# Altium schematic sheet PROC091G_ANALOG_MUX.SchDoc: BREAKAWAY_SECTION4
size 431 x 279 mm; Date: Not shown in title block; ApprovedBy: Not shown in title block; CheckedBy: Not shown in title block; Author: Not shown in title block; CompanyName: Not shown in title block; DrawnBy: Antony/Bala; Engineer: Not shown in title block; Organization: Not shown in title block; Address1: Not shown in title block; Address2: Not shown in title block; Address3: Not shown in title block; Address4: Not shown in title block; DocumentNumber: 10; Revision: Use project parameter SCH_Rev; SheetNumber: 10; SheetTotal: 12; PageSetup: Record=PageOptions¦CenterHorizontal=True¦CenterVertical=True¦PrintScale=1.00¦XCorrection=1.00¦YCorrection=1.00¦PrintKind=0¦BorderSize=5000000¦LeftOffset=0¦BottomOffset=0¦Orientation=2¦PaperLength=1000¦PaperWidth=1000¦Scale=100¦PaperSource=15¦PrintQuality=600¦MediaType=1¦DitherType=10¦PaperKind=Letter¦PrintScaleMode=1
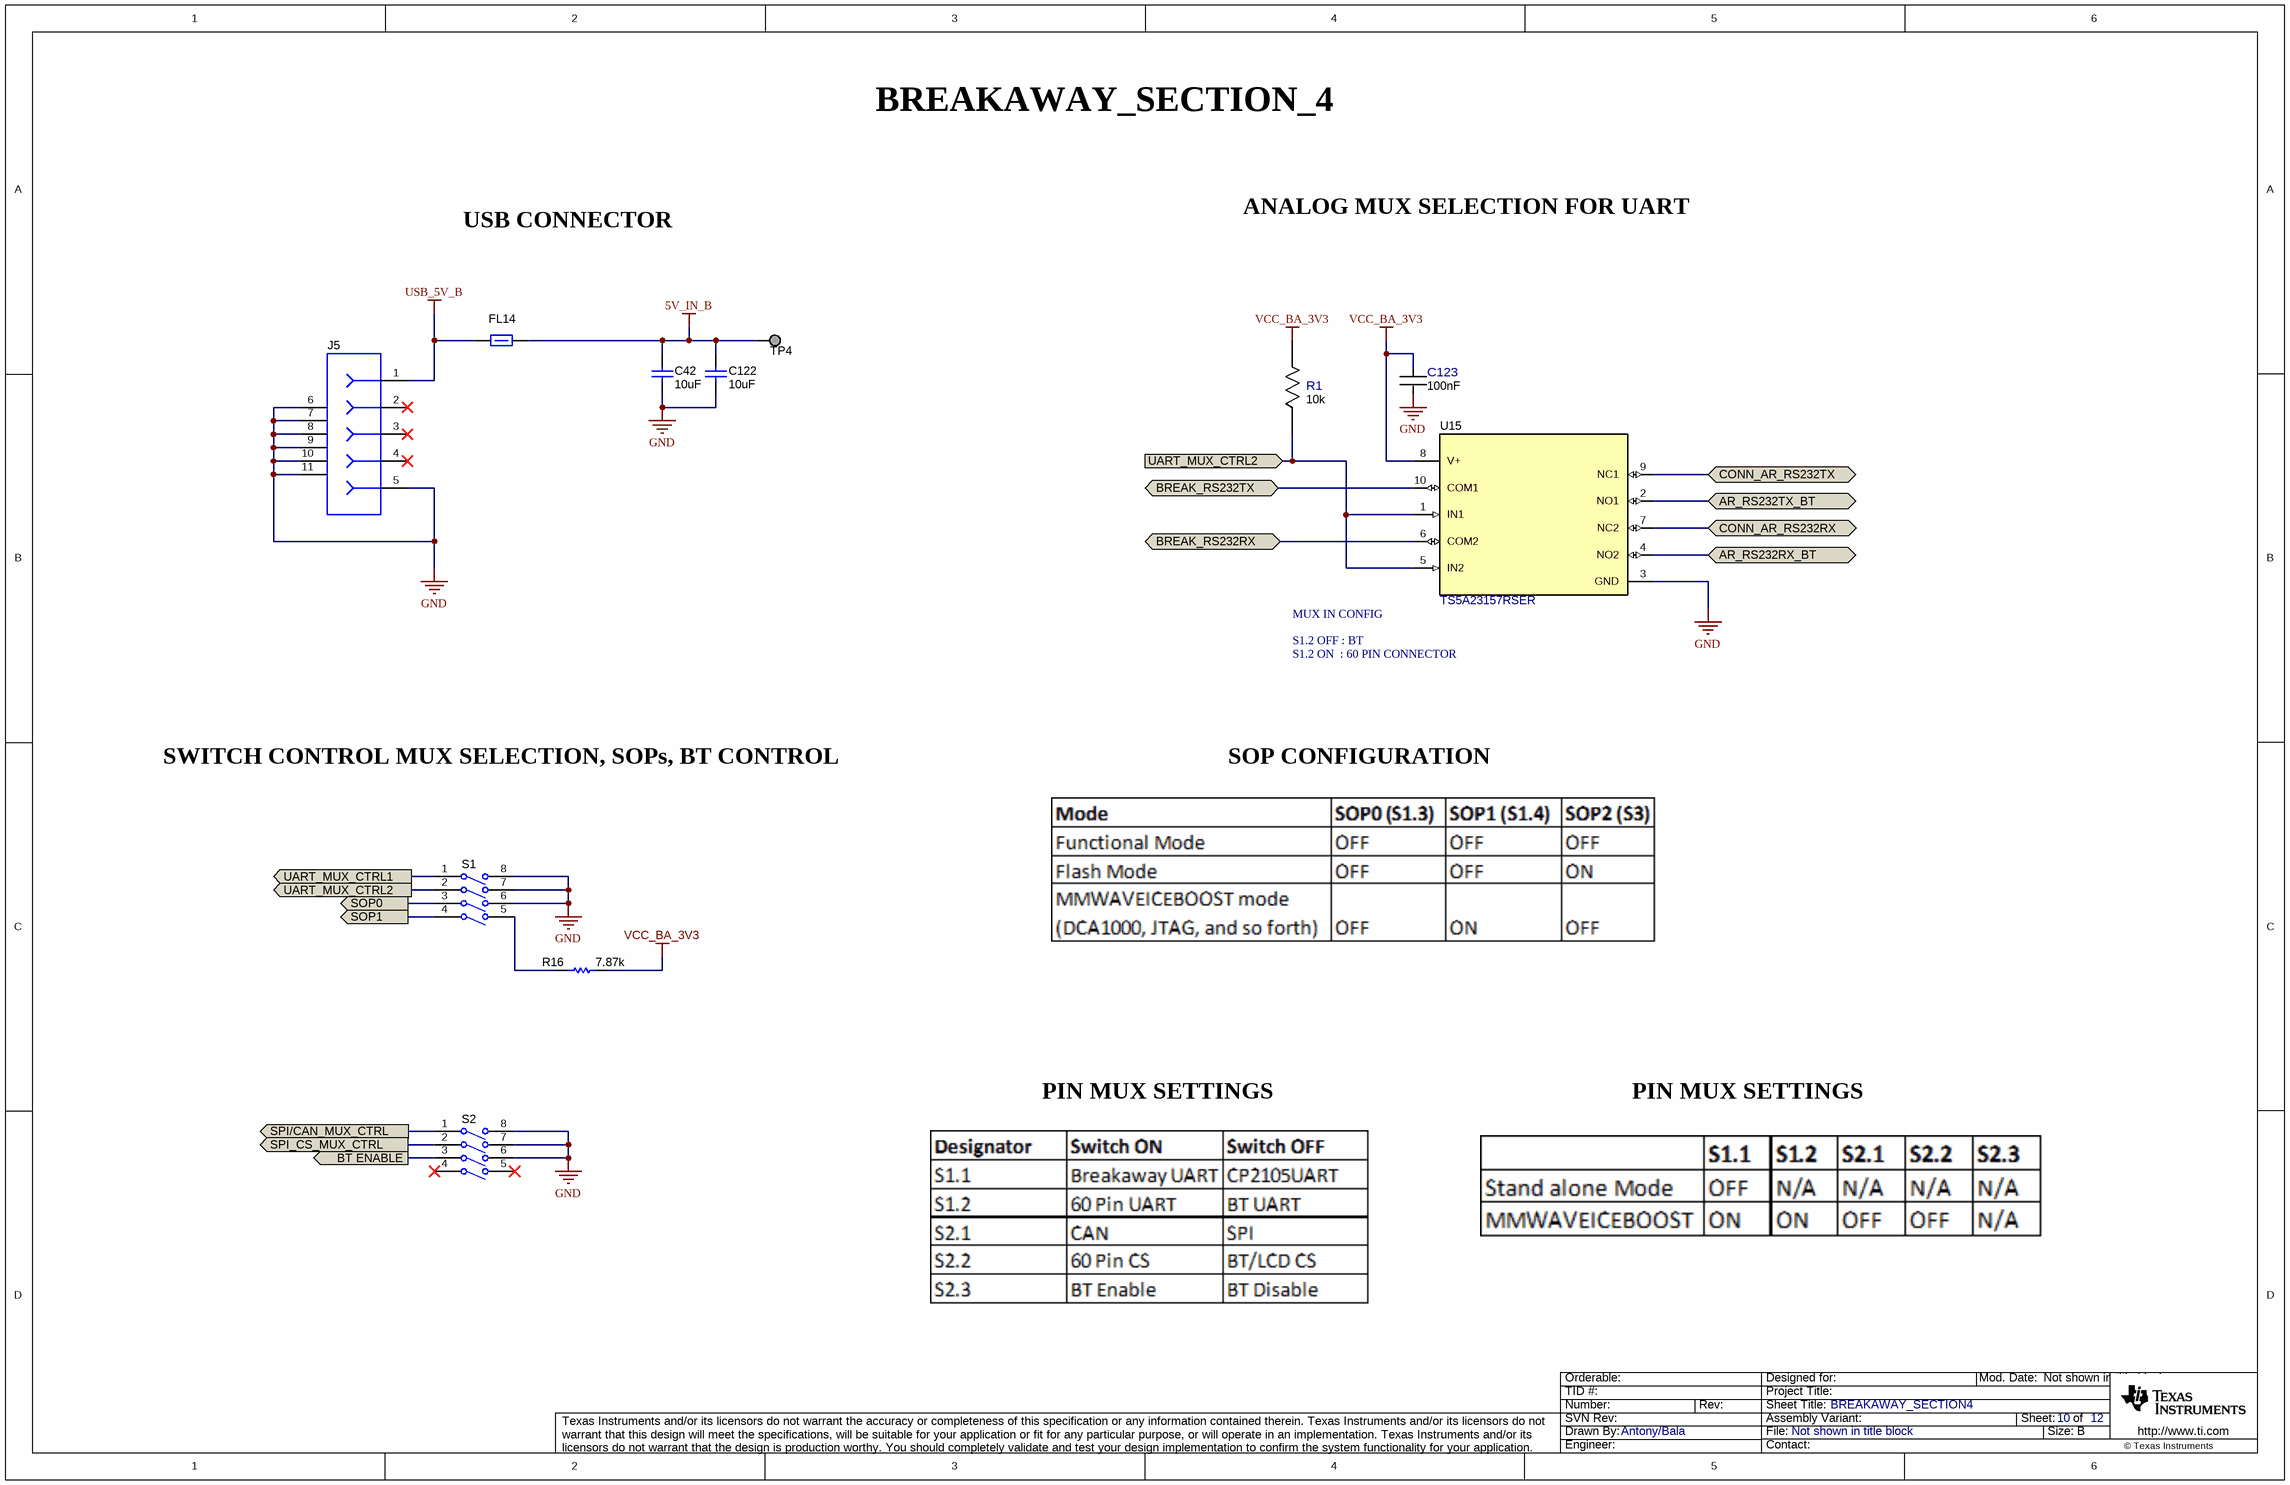
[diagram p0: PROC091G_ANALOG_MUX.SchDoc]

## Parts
C42  value 10uF  [0402_070]  (hidden comment: CL05A106MP5NUNC)
C122  value 10uF  [0402_070]  (hidden comment: CL05A106MP5NUNC)
C123  Cap_F: 100nF  [FP-GRM033R6YA104KE14D_0201 (0603 Metric)-IPC_C]  (hidden comment: GRM033R6YA104KE14D)
FL14  BLM15PD300SZ1D  [0402L]  (value not drawn)
J5  105017-0001  [CONN_105017-0001]  (value not drawn)
R1  Res_ohm: 10k  [FP-RR0306P-103-D_0201-IPC_C]  (hidden comment: RR0306P-103-D)
R16  value 7.87k  [0201L]  (hidden comment: RC0201FR-077K87L)
S1  218-4LPST  [SW_218-4LPST]  (value not drawn)
S2  218-4LPST  [SW_218-4LPST]  (value not drawn)
TP4  TESTPOINT  [TP_25MIL-SMT]  (value not drawn)  (no BOM)
U15  TS5A23157RSER  [RSE0010A]

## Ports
AR_RS232RX_BT (bidir), AR_RS232TX_BT (bidir), BREAK_RS232RX (bidir), BREAK_RS232TX (bidir), BT ENABLE (out), CONN_AR_RS232RX (bidir), CONN_AR_RS232TX (bidir), SOP0 (out), SOP1 (out), SPI/CAN_MUX_CTRL (out), SPI_CS_MUX_CTRL (out), UART_MUX_CTRL1 (out), UART_MUX_CTRL2 (in), UART_MUX_CTRL2 (out)

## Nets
5V_IN_B: C42.2 C122.1 FL14.2 TP4.1
GND: C42.1 C122.2 C123.2 J5.5 J5.6 J5.7 J5.8 J5.9 J5.10 J5.11 S1.6(B3) S1.7(B2) S1.8(B1) S2.6(B3) S2.7(B2) S2.8(B1) U15.3(GND)
USB_5V_B: FL14.1 J5.1
VCC_BA_3V3: C123.1 R1.2 R16.1 U15.8(V+)
AR_RS232RX_BT: U15.4(NO2) ; port AR_RS232RX_BT
AR_RS232TX_BT: U15.2(NO1) ; port AR_RS232TX_BT
BREAK_RS232RX: U15.6(COM2) ; port BREAK_RS232RX
BREAK_RS232TX: U15.10(COM1) ; port BREAK_RS232TX
BT ENABLE: S2.3(A3) ; port BT ENABLE
CONN_AR_RS232RX: U15.7(NC2) ; port CONN_AR_RS232RX
CONN_AR_RS232TX: U15.9(NC1) ; port CONN_AR_RS232TX
SOP0: S1.3(A3) ; port SOP0
SOP1: S1.4(A4) ; port SOP1
SPI/CAN_MUX_CTRL: S2.1(A1) ; port SPI/CAN_MUX_CTRL
SPI_CS_MUX_CTRL: S2.2(A2) ; port SPI_CS_MUX_CTRL
UART_MUX_CTRL1: S1.1(A1) ; port UART_MUX_CTRL1
UART_MUX_CTRL2: R1.1 S1.2(A2) U15.1(IN1) U15.5(IN2) ; port UART_MUX_CTRL2
NetR16_2: R16.2 S1.5(B4)

Not connected (* = marked no-connect by the designer): J5 2* 3* 4*; S2 4(A4)* 5(B4)*

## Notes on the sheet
- BREAKAWAY_SECTION_4
- USB CONNECTOR
- ANALOG MUX SELECTION FOR UART
- MUX IN CONFIG
- S1.2 ON  : 60 PIN CONNECTOR
- S1.2 OFF : BT
- SWITCH CONTROL MUX SELECTION, SOPs, BT CONTROL
- SOP CONFIGURATION
- PIN MUX SETTINGS

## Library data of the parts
C42 C122 = CMP-0006339-4: CAP, CERM, 10 uF, 10 V, +/- 20%, X5R, 0402; Manufacturer: Samsung Electro-Mechanics; AEC Category: Q200; AEC Qualified: N; Cap_Case: 0402; Cap_F: 10µF; SizeArea_mm2: 0.5; SizeAreaWB_mm2: 3; SizeX_mm: 1; SizeZ_mm: 0.6; TaMax_C: 85°C; TaMin_C: -55°C; U/M: EA; Value1: Unknown; Value2: 10V
C123 = CMP-0086440-1: Cap Ceramic 0.1uF 35V X5R 10% Pad SMD 0201 85C T/R; Manufacturer: Murata Electronics North America; AEC Qualified: No; SizeZ_mm: 0.33mm; Symbol Name: SYM-GRM033R6YA104KE14D; TempCo: 15%
FL14 = CMP-0078934-1: Inductor, Ferrite Bead, Ferrite, 2.2 A, 0.035 ohm, AEC-Q200 Grade 1, SMD; Manufacturer: MuRata; AEC Category: Q200; AEC Grade: 1; AEC Qualified: Y; DCR_ohm: 0.035; Imax_A: 2.2A; SizeArea_mm2: 0.5; SizeAreaWB_mm2: 3; SizeZ_mm: 0.6
J5 = CMP-0055293-1: Connector, Receptacle, Micro-USB Type B, R/A, Bottom Mount SMT; Manufacturer: Molex; CNHeader: FALSE; CompType: USB; CT: TRUE; Gender: Female; Green_Lifecycle: Active; Green_REACh: Passed
R1 = CMP-0088002-1: 10 kOhms ±0.5% 0.05W, 1/20W Chip Resistor 0201 (0603 Metric)  Thin Film; Manufacturer: Susumu; AEC Qualified: No; Power_W: 50mW; SizeZ_mm: 0.26mm; Symbol Name: SYM-RR0306P-103-D; TempCo: 25ppm/°C; VDC_V: 15V
R16 = CMP-0027880-1: RES, 7.87 k, 1%, 0.05 W, 0201; Manufacturer: Yageo America; AEC Category: Q200; AEC Qualified: N; EIA_Code: E96; Power_W: 50mW; SizeArea_mm2: 0.18; SizeX_mm: 0.6; SizeY_mm: 0.3; SizeZ_mm: 0.26; TempCo: 200 ppm/C; U/M: EA; Value2: 0.05W; Value_Code: 7k87; VDC_V: 25V
S1 S2 = CMP-0002128-2: Switch, Slide, SPST 4 poles, SMT; Manufacturer: CTS Electrocomponents; CurrentRating_mA: 25A; PositionCount: 4; VDC_V: 24V; SwitchFunction: Off-On
TP4 = CMP-0078143-3: TEST POINT.  No entry in BOM.
U15 = CMP-0074545-1: Dual 10-ohm SPDT Analog Switch, RSE0010A (UQFN-10); Alternate Manufacturer: Texas Instruments; CompType: IC; SizeArea_mm2: 3.0; SizeAreaWB_mm2: 7.5; SizeX_mm: 1.5; SizeY_mm: 2.0; SizeZ_mm: 0.6; U/M: EA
